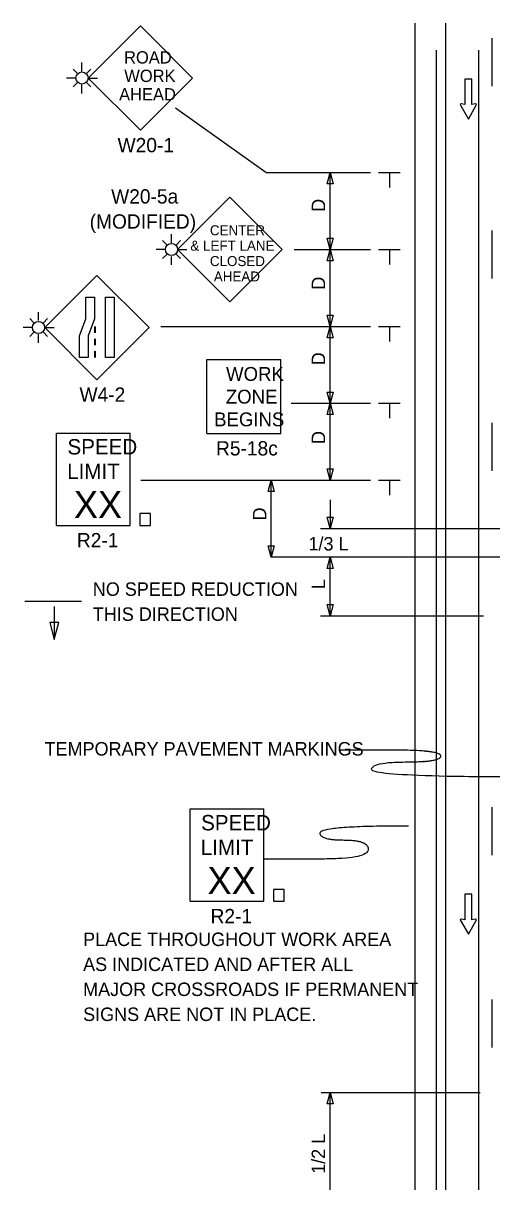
# Model space of a CAD drawing. Extents: x 16525 to 18479, y 5726 to 6926.
# Drawn here: x 16729 to 16973, y 6323 to 6926 of the extents above; entities that cross this region are included whole.
import ezdxf

# ---------------------------------------------------------------- set-up
doc = ezdxf.new("R2010")
doc.units = 0
for name, color, linetype in [('ALI_LEGAL_EX', 7, 'Continuous'), ('MT_SCRATCH_LEVEL_E', 7, 'Continuous'), ('PAVT_EDGE_EX', 7, 'Continuous'), ('TRAFFIC_SIGNS_PR', 7, 'Continuous'), ('TYPICAL_TEXT_DIMEN_PR', 7, 'Continuous')]:
    doc.layers.add(name, color=color, linetype=linetype)

msp = doc.modelspace()

# ---------------------------------------------------------------- linework, layer by layer
at = {"layer": 'ALI_LEGAL_EX'}
for points in [[(16973, 6918.24), (16973, 6893.24)], [(16973, 6818.24), (16973, 6793.24)], [(16973, 6818.24), (16973, 6793.24)], [(16973, 6718.24), (16973, 6693.24)], [(16973, 6718.24), (16973, 6693.24)], [(16973, 6518.24), (16973, 6493.24)], [(16973, 6518.24), (16973, 6493.24)], [(16973, 6418.24), (16973, 6393.24)], [(16973, 6418.24), (16973, 6393.24)]]:
    msp.add_lwpolyline(points, dxfattribs=at)
at = {"layer": 'MT_SCRATCH_LEVEL_E'}
for p, q in [((16962.67, 6897.03), (16958.93, 6897.03)), ((16958.93, 6897.03), (16958.93, 6883.77)), ((16962.67, 6897.03), (16958.93, 6897.03)), ((16958.93, 6897.03), (16958.93, 6883.77)), ((16962.67, 6883.77), (16962.67, 6897.03)), ((16962.67, 6883.77), (16962.67, 6897.03)), ((16956.67, 6883.4), (16960.82, 6876.16)), ((16956.67, 6883.4), (16960.82, 6876.16)), ((16958.93, 6883.77), (16957.15, 6884.09)), ((16958.93, 6883.77), (16957.15, 6884.09)), ((16960.82, 6876.16), (16964.93, 6883.4)), ((16960.82, 6876.16), (16964.93, 6883.4)), ((16964.44, 6884.09), (16962.67, 6883.77)), ((16964.44, 6884.09), (16962.67, 6883.77)), ((16962.67, 6473.03), (16958.93, 6473.03)), ((16958.93, 6473.03), (16958.93, 6459.77)), ((16962.67, 6473.03), (16958.93, 6473.03)), ((16958.93, 6473.03), (16958.93, 6459.77)), ((16962.67, 6459.77), (16962.67, 6473.03)), ((16962.67, 6459.77), (16962.67, 6473.03)), ((16956.67, 6459.4), (16960.82, 6452.16)), ((16956.67, 6459.4), (16960.82, 6452.16)), ((16958.93, 6459.77), (16957.15, 6460.09)), ((16958.93, 6459.77), (16957.15, 6460.09)), ((16960.82, 6452.16), (16964.93, 6459.4)), ((16960.82, 6452.16), (16964.93, 6459.4)), ((16964.44, 6460.09), (16962.67, 6459.77)), ((16964.44, 6460.09), (16962.67, 6459.77))]:
    msp.add_line(p, q, dxfattribs=at)
for centre, start, end in [((16957.08, 6883.63), 80.03619, 209.77312), ((16957.08, 6883.63), 80.03619, 209.77312), ((16964.52, 6883.63), 330.42484, 99.96381), ((16964.52, 6883.63), 330.42484, 99.96381), ((16957.08, 6459.63), 80.03619, 209.77312), ((16957.08, 6459.63), 80.03619, 209.77312), ((16964.52, 6459.63), 330.42484, 99.96381), ((16964.52, 6459.63), 330.42484, 99.96381)]:
    msp.add_arc(centre, 0.463, start, end, dxfattribs=at)
at = {"layer": 'PAVT_EDGE_EX'}
for p, q in [((16933, 6926.09), (16933, 6125.43)), ((16949, 6926.09), (16949, 6125.43)), ((16944.07, 6912.1), (16944.07, 6082.91)), ((16966.07, 6912.1), (16966.07, 6082.91))]:
    msp.add_line(p, q, dxfattribs=at)
at = {"layer": 'TRAFFIC_SIGNS_PR'}
for p, q in [((16790.28, 6924.75), (16763.1, 6897.56)), ((16817.47, 6897.56), (16790.28, 6924.75)), ((16757.43, 6900.07), (16755.32, 6902.18)), ((16759.94, 6901.12), (16759.94, 6905.62)), ((16762.46, 6900.07), (16764.57, 6902.18)), ((16756.79, 6897.56), (16751.95, 6897.56)), ((16757.43, 6895.05), (16755.32, 6892.94)), ((16762.46, 6895.05), (16764.56, 6892.94)), ((16763.1, 6897.56), (16767.98, 6897.56)), ((16763.1, 6897.56), (16790.28, 6870.37)), ((16790.28, 6870.37), (16817.47, 6897.56)), ((16759.94, 6889.59), (16759.94, 6894.01)), ((16836.81, 6835.53), (16809.63, 6808.35)), ((16864, 6808.35), (16836.81, 6835.53)), ((16806.47, 6811.9), (16806.47, 6816.4)), ((16803.96, 6810.86), (16801.85, 6812.97)), ((16808.99, 6810.86), (16811.09, 6812.97)), ((16803.32, 6808.35), (16798.48, 6808.35)), ((16803.96, 6805.84), (16801.85, 6803.73)), ((16806.47, 6800.38), (16806.47, 6804.79)), ((16808.99, 6805.84), (16811.09, 6803.73)), ((16809.63, 6808.35), (16814.51, 6808.35)), ((16809.63, 6808.35), (16836.81, 6781.16)), ((16836.81, 6781.16), (16864, 6808.35)), ((16767.7, 6794.91), (16740.55, 6767.76)), ((16794.85, 6767.76), (16767.7, 6794.91)), ((16737.36, 6771.35), (16737.36, 6775.85)), ((16734.84, 6770.3), (16732.74, 6772.41)), ((16739.87, 6770.3), (16741.98, 6772.41)), ((16766.45, 6768.25), (16766.45, 6765.05)), ((16766.85, 6768.25), (16766.85, 6765.05)), ((16734.2, 6767.79), (16729.37, 6767.79)), ((16734.84, 6765.28), (16732.74, 6763.17)), ((16737.36, 6759.83), (16737.36, 6764.24)), ((16739.87, 6765.28), (16741.98, 6763.17)), ((16740.51, 6767.79), (16745.39, 6767.79)), ((16740.55, 6767.76), (16767.7, 6740.6)), ((16767.7, 6740.6), (16794.85, 6767.76)), ((16766.45, 6761.85), (16766.45, 6758.65)), ((16766.85, 6761.85), (16766.85, 6758.65)), ((16766.45, 6755.45), (16766.45, 6752.25)), ((16766.85, 6755.45), (16766.85, 6752.25)), ((16824.84, 6712.66), (16824.84, 6751.06)), ((16824.84, 6751.06), (16863.24, 6751.06)), ((16863.24, 6712.66), (16863.24, 6751.06)), ((16746.63, 6712.88), (16785.03, 6712.88)), ((16746.63, 6664.88), (16746.63, 6712.88)), ((16785.03, 6664.88), (16785.03, 6712.88)), ((16824.84, 6712.66), (16863.24, 6712.66)), ((16746.63, 6664.88), (16785.03, 6664.88)), ((16816.1, 6517.35), (16854.5, 6517.35)), ((16816.1, 6469.35), (16816.1, 6517.35)), ((16854.5, 6469.35), (16854.5, 6517.35)), ((16816.1, 6469.35), (16854.5, 6469.35))]:
    msp.add_line(p, q, dxfattribs=at)
for points in [[(16766.45, 6783.49), (16766.45, 6772.31), (16763.11, 6763.43), (16763.11, 6752.25), (16758.61, 6752.25), (16758.61, 6763.43), (16761.96, 6772.31), (16761.96, 6783.49)], [(16776.59, 6783.49), (16776.59, 6752.25), (16772.09, 6752.25), (16772.09, 6783.49)], [(16790.04, 6664.88), (16795.64, 6664.88), (16795.64, 6671.05), (16790.04, 6671.05)], [(16859.52, 6469.35), (16865.11, 6469.35), (16865.11, 6475.52), (16859.52, 6475.52)]]:
    msp.add_lwpolyline(points, close=True, dxfattribs=at)
for centre in [(16759.94, 6897.56), (16806.47, 6808.35), (16737.36, 6767.79)]:
    msp.add_circle(centre, 3.15, dxfattribs=at)
at = {"layer": 'TYPICAL_TEXT_DIMEN_PR'}
for p, q in [((16855.57, 6848.35), (16808.54, 6881.96)), ((16855.57, 6848.35), (16909.9, 6848.35)), ((16883.9, 6848.35), (16909.9, 6848.35)), ((16887.33, 6842.49), (16888.9, 6848.35)), ((16888.9, 6808.35), (16888.9, 6848.35)), ((16888.9, 6848.35), (16890.47, 6842.49)), ((16914.15, 6848.35), (16925.4, 6848.35)), ((16919.78, 6848.35), (16919.78, 6840.56)), ((16888.9, 6842.49), (16887.33, 6842.49)), ((16890.47, 6842.49), (16888.9, 6842.49)), ((16888.9, 6808.35), (16887.33, 6814.21)), ((16887.33, 6814.21), (16888.9, 6814.21)), ((16888.9, 6814.21), (16890.47, 6814.21)), ((16890.47, 6814.21), (16888.9, 6808.35)), ((16870.24, 6808.35), (16909.9, 6808.35)), ((16883.9, 6808.35), (16909.9, 6808.35)), ((16887.33, 6802.49), (16888.9, 6808.35)), ((16888.9, 6808.35), (16890.47, 6802.49)), ((16888.9, 6768.35), (16888.9, 6808.35)), ((16914.15, 6808.35), (16925.4, 6808.35)), ((16919.78, 6808.35), (16919.78, 6800.56)), ((16888.9, 6802.49), (16887.33, 6802.49)), ((16890.47, 6802.49), (16888.9, 6802.49)), ((16888.9, 6768.35), (16887.33, 6774.21)), ((16887.33, 6774.21), (16888.9, 6774.21)), ((16888.9, 6774.21), (16890.47, 6774.21)), ((16890.47, 6774.21), (16888.9, 6768.35)), ((16800.9, 6768.35), (16909.9, 6768.35)), ((16883.9, 6768.35), (16909.9, 6768.35)), ((16887.33, 6762.49), (16888.9, 6768.35)), ((16888.9, 6768.35), (16890.47, 6762.49)), ((16888.9, 6728.35), (16888.9, 6768.35)), ((16914.15, 6768.35), (16925.4, 6768.35)), ((16919.78, 6768.35), (16919.78, 6760.56)), ((16888.9, 6762.49), (16887.33, 6762.49)), ((16890.47, 6762.49), (16888.9, 6762.49)), ((16888.9, 6728.35), (16887.33, 6734.21)), ((16887.33, 6734.21), (16888.9, 6734.21)), ((16888.9, 6734.21), (16890.47, 6734.21)), ((16890.47, 6734.21), (16888.9, 6728.35)), ((16868.74, 6728.35), (16909.9, 6728.35)), ((16887.33, 6722.49), (16888.9, 6728.35)), ((16888.9, 6728.35), (16890.47, 6722.49)), ((16888.9, 6688.35), (16888.9, 6728.35)), ((16914.15, 6728.35), (16925.4, 6728.35)), ((16919.78, 6728.35), (16919.78, 6720.56)), ((16888.9, 6722.49), (16887.33, 6722.49)), ((16890.47, 6722.49), (16888.9, 6722.49)), ((16888.9, 6688.35), (16887.33, 6694.21)), ((16887.33, 6694.21), (16888.9, 6694.21)), ((16888.9, 6694.21), (16890.47, 6694.21)), ((16890.47, 6694.21), (16888.9, 6688.35)), ((16790.46, 6688.35), (16909.9, 6688.35)), ((16856.75, 6682.49), (16858.32, 6688.35)), ((16858.32, 6688.35), (16859.89, 6682.49)), ((16858.32, 6648.35), (16858.32, 6688.35)), ((16914.15, 6688.35), (16925.4, 6688.35)), ((16919.78, 6688.35), (16919.78, 6680.56)), ((16858.32, 6682.49), (16856.75, 6682.49)), ((16859.89, 6682.49), (16858.32, 6682.49)), ((16888.9, 6678.19), (16888.9, 6663.27)), ((16888.9, 6663.27), (16887.33, 6669.13)), ((16887.33, 6669.13), (16888.9, 6669.13)), ((16888.9, 6669.13), (16890.47, 6669.13)), ((16890.47, 6669.13), (16888.9, 6663.27)), ((16883.9, 6663.27), (17013.03, 6663.27)), ((16858.32, 6648.35), (16856.75, 6654.21)), ((16856.75, 6654.21), (16858.32, 6654.21)), ((16858.32, 6654.21), (16859.89, 6654.21)), ((16859.89, 6654.21), (16858.32, 6648.35)), ((16989.81, 6648.35), (16858.32, 6648.35)), ((16887.33, 6642.49), (16888.9, 6648.35)), ((16888.9, 6617.81), (16888.9, 6648.35)), ((16888.9, 6648.35), (16890.47, 6642.49)), ((16888.9, 6642.49), (16887.33, 6642.49)), ((16890.47, 6642.49), (16888.9, 6642.49)), ((16759.72, 6625.2), (16730.28, 6625.2)), ((16888.9, 6617.81), (16887.33, 6623.68)), ((16887.33, 6623.68), (16888.9, 6623.68)), ((16888.9, 6623.68), (16890.47, 6623.68)), ((16890.47, 6623.68), (16888.9, 6617.81)), ((16745.54, 6622.7), (16745.54, 6605.58)), ((16883.9, 6617.81), (16968.72, 6617.81)), ((16745.54, 6614.37), (16743.19, 6614.37)), ((16743.19, 6614.37), (16745.54, 6605.58)), ((16745.54, 6605.58), (16747.9, 6614.37)), ((16747.9, 6614.37), (16745.54, 6614.37)), ((16884.27, 6369.82), (16966.99, 6369.82)), ((16887.33, 6363.96), (16888.9, 6369.82)), ((16888.9, 6369.82), (16890.47, 6363.96)), ((16888.9, 6311.18), (16888.9, 6369.82)), ((16888.9, 6363.96), (16887.33, 6363.96)), ((16890.47, 6363.96), (16888.9, 6363.96))]:
    msp.add_line(p, q, dxfattribs=at)
for points in [[(16995.27, 6533.91), (16910.49, 6533.91), (16910.49, 6541.79), (16946.45, 6541.79), (16946.45, 6547.94), (16898.15, 6547.94), (16894.21, 6547.94)], [(16929.72, 6508.48), (16883.63, 6508.48), (16883.63, 6501.21), (16908.8, 6501.21), (16908.8, 6491.31), (16859.16, 6491.31), (16854.23, 6491.31)]]:
    msp.add_open_spline(points, degree=2, dxfattribs=at)

# ---------------------------------------------------------------- texts
at = {"layer": 'TRAFFIC_SIGNS_PR'}
for s, height, p in [('ROAD', 6.408, (16781.81, 6905.1)), ('WORK', 6.408, (16781.92, 6895.49)), ('AHEAD', 6.408, (16779.23, 6885.88)), ('W20-1', 7.449, (16778.44, 6858.92)), ('W20-5a', 7.449, (16775.09, 6832.26)), ('(MODIFIED)', 7.449, (16763.93, 6819.21)), ('CENTER', 5.206, (16826.43, 6815.76)), ('& LEFT LANE', 5.2065, (16816.29, 6807.75)), ('CLOSED', 5.206, (16826.44, 6799.74)), ('AHEAD', 5.206, (16828.47, 6791.73)), ('WORK', 7.217, (16834.84, 6740.02)), ('W4-2', 7.44, (16758.66, 6729.16)), ('ZONE', 7.217, (16834.72, 6728.21)), ('BEGINS', 7.217, (16828.65, 6716.4)), ('SPEED', 8, (16752.39, 6701.74)), ('R5-18c', 7.44, (16829.65, 6701.22)), ('LIMIT', 8, (16752.23, 6688.94)), ('XX', 14.031, (16755.74, 6668.64)), ('R2-1', 7.44, (16757.3, 6653.44)), ('SPEED', 8, (16821.87, 6506.21)), ('LIMIT', 8, (16821.7, 6493.41)), ('XX', 14.031, (16825.21, 6473.11)), ('R2-1', 7.44, (16826.78, 6457.91)), ('PLACE THROUGHOUT WORK AREA', 7, (16760.52, 6446.06)), ('AS INDICATED AND AFTER ALL', 7, (16760.52, 6433.06)), ('MAJOR CROSSROADS IF PERMANENT', 7, (16760.52, 6420.06)), ('SIGNS ARE NOT IN PLACE.', 7, (16760.52, 6407.06))]:
    msp.add_text(s, height=height, dxfattribs=at).set_placement(p)
at = {"layer": 'TYPICAL_TEXT_DIMEN_PR'}
for s, p in [('D', (16886.34, 6827.94)), ('D', (16886.34, 6787.46)), ('D', (16886.34, 6748.13)), ('D', (16886.34, 6707.19)), ('D', (16855.76, 6667.42)), ('L', (16886.34, 6631.68)), ('1/2 L', (16886.34, 6327.55))]:
    msp.add_text(s, height=7, rotation=90, dxfattribs=at).set_placement(p)
for s, p in [('1/3 L', (16877.68, 6651.8)), ('NO SPEED REDUCTION', (16765.56, 6628.21)), ('THIS DIRECTION', (16765.56, 6615.21)), ('TEMPORARY PAVEMENT MARKINGS', (16740.47, 6545.15))]:
    msp.add_text(s, height=7, dxfattribs=at).set_placement(p)

doc.saveas('drawing.dxf')
